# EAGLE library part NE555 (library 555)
General purpose bipolar Timer
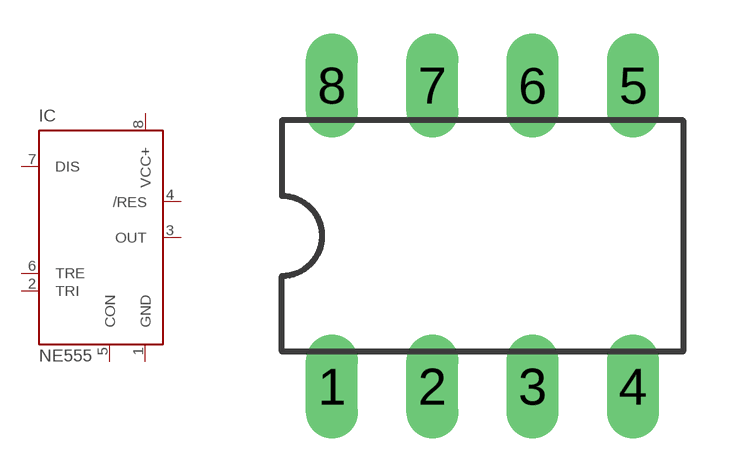
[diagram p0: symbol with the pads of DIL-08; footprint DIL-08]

Designator prefix IC

## NE555  [DIL-08]
1  GND  pwr
2  TRI  in
3  OUT  out
4  /RES  in
5  CON  in
6  TRE  in
7  DIS  in
8  VCC+  pwr

## Footprint DIL-08 (pad centres in mm)
Dual In Line Package
drill 0.813 long: 1 -3.81,-3.81; 2 -1.27,-3.81; 3 1.27,-3.81; 4 3.81,-3.81; 5 3.81,3.81; 6 1.27,3.81; 7 -1.27,3.81; 8 -3.81,3.81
